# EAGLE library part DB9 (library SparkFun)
DB9 Connector Standard DB9 (D-Sub 9) serial connector. Can be used for CAN bus as well as RS485 and RS232. Footprint production proven. Spark Fun Electronics SKU : PType-DB9-PCB
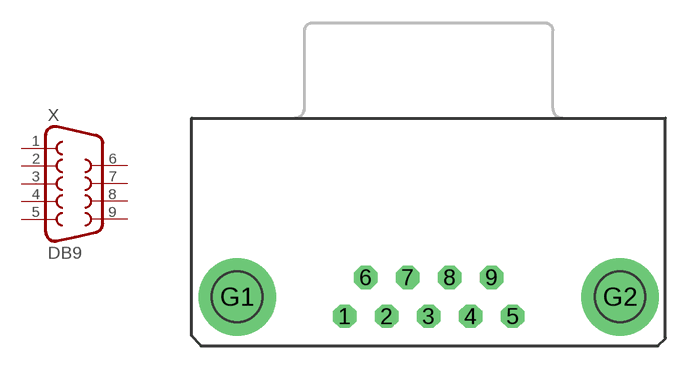
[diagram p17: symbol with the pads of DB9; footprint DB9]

Designator prefix X

## DB9  [DB9]
1  1  pas
2  2  pas
3  3  pas
4  4  pas
5  5  pas
6  6  pas
7  7  pas
8  8  pas
9  9  pas

## Footprint DB9 (pad centres in mm)
SUB-D
drill 1.016 octagon: 1 -5.486,-1.27; 2 -2.743,-1.27; 3 0,-1.27; 4 2.743,-1.27; 5 5.486,-1.27; 6 -4.115,1.27; 7 -1.372,1.27; 8 1.372,1.27; 9 4.115,1.27
drill 3.302 pad 5.08 round: G1 -12.522,0; G2 12.522,0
